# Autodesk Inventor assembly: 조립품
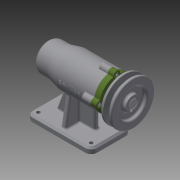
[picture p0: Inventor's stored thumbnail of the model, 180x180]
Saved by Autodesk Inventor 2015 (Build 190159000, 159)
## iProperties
Created: 2019-07
Part Number: 조립품
Document SubType Name: Assembly
Designer: now
Author: now
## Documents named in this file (12)
- C:\Users\now\Desktop\490704V1026 (1)\조립품.iam
- C:\Users\now\Desktop\490704V1026 (1)\V벨트풀리.ipt
- C:\Users\now\Desktop\490704V1026 (1)\멈춤나사 M3.ipt
- C:\Users\now\Desktop\490704V1026 (1)\베어링 6004.ipt
- C:\Users\now\Desktop\490704V1026 (1)\베어링 51202.ipt
- C:\Users\now\Desktop\490704V1026 (1)\본체.ipt
- C:\Users\now\Desktop\490704V1026 (1)\볼트 M4.ipt
- C:\Users\now\Desktop\490704V1026 (1)\어댑터슬리브.ipt
- C:\Users\now\Desktop\490704V1026 (1)\오일 실.ipt
- C:\Users\now\Desktop\490704V1026 (1)\축.ipt
- C:\Users\now\Desktop\490704V1026 (1)\커버.ipt
- C:\Users\now\Desktop\490704V1026 (1)\키 5 x 5 x 16.ipt
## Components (1 placed, 1 different names)
1. V벨트풀리:1
